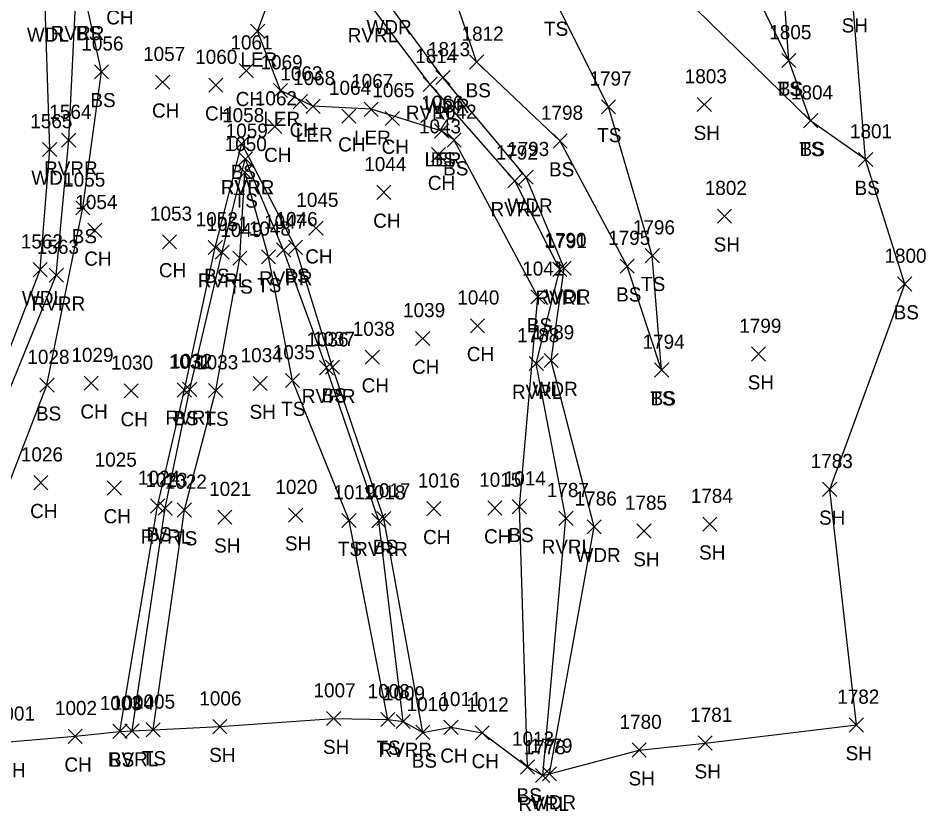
# Model space of a CAD drawing. Extents: x 1600281 to 1602254, y 862855 to 863227.
# Drawn here: x 1602106.5 to 1602234.8, y 862869.5 to 862981.5 of the extents above; entities that cross this region are included whole.
import ezdxf

# ---------------------------------------------------------------- set-up
doc = ezdxf.new("R2010")
doc.units = 0
for name, color, linetype in [('L_A', 7, 'Continuous'), ('L_I', 7, 'Continuous'), ('L_TIC', 7, 'Continuous'), ('LARO', 7, 'Continuous'), ('LAWA', 7, 'Continuous'), ('LAWE', 7, 'Continuous'), ('LELB', 7, 'Continuous'), ('LSOGP', 7, 'Continuous')]:
    doc.layers.add(name, color=color, linetype=linetype)

msp = doc.modelspace()

# ---------------------------------------------------------------- linework, layer by layer
at = {"layer": 'L_TIC'}
for points in [[(1602139.35, 862978.68), (1602141.35, 862980.68)], [(1602141.35, 862978.68), (1602139.35, 862980.68)], [(1602170.3, 862974.32), (1602172.3, 862976.32)], [(1602172.3, 862974.32), (1602170.3, 862976.32)], [(1602214.42, 862974.54), (1602216.42, 862976.54)], [(1602216.42, 862974.54), (1602214.42, 862976.54)], [(1602214.42, 862974.54), (1602216.42, 862976.54)], [(1602216.42, 862974.54), (1602214.42, 862976.54)], [(1602117.28, 862972.93), (1602119.28, 862974.93)], [(1602119.28, 862972.93), (1602117.28, 862974.93)], [(1602137.76, 862973.09), (1602139.76, 862975.09)], [(1602139.76, 862973.09), (1602137.76, 862975.09)], [(1602125.94, 862971.46), (1602127.94, 862973.46)], [(1602127.94, 862971.46), (1602125.94, 862973.46)], [(1602165.54, 862972.13), (1602167.54, 862974.13)], [(1602167.54, 862972.13), (1602165.54, 862974.13)], [(1602133.44, 862971.05), (1602135.44, 862973.05)], [(1602135.44, 862971.05), (1602133.44, 862973.05)], [(1602142.59, 862970.28), (1602144.59, 862972.28)], [(1602144.59, 862970.28), (1602142.59, 862972.28)], [(1602163.73, 862971.16), (1602165.73, 862973.16)], [(1602165.73, 862971.16), (1602163.73, 862973.16)], [(1602145.38, 862968.71), (1602147.38, 862970.71)], [(1602147.38, 862968.71), (1602145.38, 862970.71)], [(1602147.17, 862968.06), (1602149.17, 862970.06)], [(1602149.17, 862968.06), (1602147.17, 862970.06)], [(1602155.39, 862967.63), (1602157.39, 862969.63)], [(1602157.39, 862967.63), (1602155.39, 862969.63)], [(1602188.93, 862967.99), (1602190.93, 862969.99)], [(1602190.93, 862967.99), (1602188.93, 862969.99)], [(1602202.47, 862968.3), (1602204.47, 862970.3)], [(1602204.47, 862968.3), (1602202.47, 862970.3)], [(1602152.25, 862966.67), (1602154.25, 862968.67)], [(1602154.25, 862966.67), (1602152.25, 862968.67)], [(1602158.38, 862966.34), (1602160.38, 862968.34)], [(1602160.38, 862966.34), (1602158.38, 862968.34)], [(1602141.78, 862965.19), (1602143.78, 862967.19)], [(1602143.78, 862965.19), (1602141.78, 862967.19)], [(1602217.49, 862966.02), (1602219.49, 862968.02)], [(1602219.49, 862966.02), (1602217.49, 862968.02)], [(1602217.49, 862966.02), (1602219.49, 862968.02)], [(1602219.49, 862966.02), (1602217.49, 862968.02)], [(1602165.36, 862964.56), (1602167.36, 862966.56)], [(1602167.36, 862964.56), (1602165.36, 862966.56)], [(1602165.36, 862964.56), (1602167.36, 862966.56)], [(1602167.36, 862964.56), (1602165.36, 862966.56)], [(1602112.66, 862963.28), (1602114.66, 862965.28)], [(1602114.66, 862963.28), (1602112.66, 862965.28)], [(1602137.1, 862962.8), (1602139.1, 862964.8)], [(1602139.1, 862962.8), (1602137.1, 862964.8)], [(1602137.1, 862962.8), (1602139.1, 862964.8)], [(1602139.1, 862962.8), (1602137.1, 862964.8)], [(1602167.13, 862963.29), (1602169.13, 862965.29)], [(1602169.13, 862963.29), (1602167.13, 862965.29)], [(1602182.09, 862963.15), (1602184.09, 862965.15)], [(1602184.09, 862963.15), (1602182.09, 862965.15)], [(1602109.97, 862961.96), (1602111.97, 862963.96)], [(1602111.97, 862961.96), (1602109.97, 862963.96)], [(1602164.91, 862961.23), (1602166.91, 862963.23)], [(1602166.91, 862961.23), (1602164.91, 862963.23)], [(1602137.61, 862960.62), (1602139.61, 862962.62)], [(1602139.61, 862960.62), (1602137.61, 862962.62)], [(1602137.61, 862960.62), (1602139.61, 862962.62)], [(1602139.61, 862960.62), (1602137.61, 862962.62)], [(1602225.26, 862960.53), (1602227.26, 862962.53)], [(1602227.26, 862960.53), (1602225.26, 862962.53)], [(1602137.56, 862958.73), (1602139.56, 862960.73)], [(1602139.56, 862958.73), (1602137.56, 862960.73)], [(1602137.56, 862958.73), (1602139.56, 862960.73)], [(1602139.56, 862958.73), (1602137.56, 862960.73)], [(1602175.69, 862957.52), (1602177.69, 862959.52)], [(1602177.69, 862957.52), (1602175.69, 862959.52)], [(1602177.29, 862958.03), (1602179.29, 862960.03)], [(1602179.29, 862958.03), (1602177.29, 862960.03)], [(1602157.19, 862955.89), (1602159.19, 862957.89)], [(1602159.19, 862955.89), (1602157.19, 862957.89)], [(1602114.65, 862953.7), (1602116.65, 862955.7)], [(1602116.65, 862953.7), (1602114.65, 862955.7)], [(1602205.31, 862952.53), (1602207.31, 862954.53)], [(1602207.31, 862952.53), (1602205.31, 862954.53)], [(1602147.59, 862950.84), (1602149.59, 862952.84)], [(1602149.59, 862950.84), (1602147.59, 862952.84)], [(1602116.36, 862950.53), (1602118.36, 862952.53)], [(1602118.36, 862950.53), (1602116.36, 862952.53)], [(1602126.91, 862948.89), (1602128.91, 862950.89)], [(1602128.91, 862948.89), (1602126.91, 862950.89)], [(1602133.37, 862948.1), (1602135.37, 862950.1)], [(1602135.37, 862948.1), (1602133.37, 862950.1)], [(1602144.7, 862948.12), (1602146.7, 862950.12)], [(1602146.7, 862948.12), (1602144.7, 862950.12)], [(1602134.34, 862947.45), (1602136.34, 862949.45)], [(1602136.34, 862947.45), (1602134.34, 862949.45)], [(1602143.03, 862947.74), (1602145.03, 862949.74)], [(1602145.03, 862947.74), (1602143.03, 862949.74)], [(1602195.12, 862946.95), (1602197.12, 862948.95)], [(1602197.12, 862946.95), (1602195.12, 862948.95)], [(1602136.85, 862946.58), (1602138.85, 862948.58)], [(1602138.85, 862946.58), (1602136.85, 862948.58)], [(1602140.88, 862946.78), (1602142.88, 862948.78)], [(1602142.88, 862946.78), (1602140.88, 862948.78)], [(1602108.63, 862944.96), (1602110.63, 862946.96)], [(1602110.63, 862944.96), (1602108.63, 862946.96)], [(1602182.06, 862945.01), (1602184.06, 862947.01)], [(1602184.06, 862945.01), (1602182.06, 862947.01)], [(1602182.65, 862945.17), (1602184.65, 862947.17)], [(1602184.65, 862945.17), (1602182.65, 862947.17)], [(1602191.57, 862945.47), (1602193.57, 862947.47)], [(1602193.57, 862945.47), (1602191.57, 862947.47)], [(1602110.9, 862944.19), (1602112.9, 862946.19)], [(1602112.9, 862944.19), (1602110.9, 862946.19)], [(1602230.78, 862942.94), (1602232.78, 862944.94)], [(1602232.78, 862942.94), (1602230.78, 862944.94)], [(1602178.94, 862941.12), (1602180.94, 862943.12)], [(1602180.94, 862941.12), (1602178.94, 862943.12)], [(1602170.42, 862937.04), (1602172.42, 862939.04)], [(1602172.42, 862937.04), (1602170.42, 862939.04)], [(1602162.68, 862935.25), (1602164.68, 862937.25)], [(1602164.68, 862935.25), (1602162.68, 862937.25)], [(1602210.12, 862933.04), (1602212.12, 862935.04)], [(1602212.12, 862933.04), (1602210.12, 862935.04)], [(1602155.56, 862932.61), (1602157.56, 862934.61)], [(1602157.56, 862932.61), (1602155.56, 862934.61)], [(1602178.73, 862931.7), (1602180.73, 862933.7)], [(1602180.73, 862931.7), (1602178.73, 862933.7)], [(1602180.84, 862932.12), (1602182.84, 862934.12)], [(1602182.84, 862932.12), (1602180.84, 862934.12)], [(1602149.09, 862931.11), (1602151.09, 862933.11)], [(1602151.09, 862931.11), (1602149.09, 862933.11)], [(1602149.94, 862931.2), (1602151.94, 862933.2)], [(1602151.94, 862931.2), (1602149.94, 862933.2)], [(1602196.44, 862930.78), (1602198.44, 862932.78)], [(1602198.44, 862930.78), (1602196.44, 862932.78)], [(1602196.44, 862930.78), (1602198.44, 862932.78)], [(1602198.44, 862930.78), (1602196.44, 862932.78)], [(1602115.82, 862928.92), (1602117.82, 862930.92)], [(1602117.82, 862928.92), (1602115.82, 862930.92)], [(1602139.72, 862928.88), (1602141.72, 862930.88)], [(1602141.72, 862928.88), (1602139.72, 862930.88)], [(1602144.27, 862929.3), (1602146.27, 862931.3)], [(1602146.27, 862929.3), (1602144.27, 862931.3)], [(1602109.59, 862928.64), (1602111.59, 862930.64)], [(1602111.59, 862928.64), (1602109.59, 862930.64)], [(1602121.49, 862927.83), (1602123.49, 862929.83)], [(1602123.49, 862927.83), (1602121.49, 862929.83)], [(1602129, 862927.97), (1602131, 862929.97)], [(1602131, 862927.97), (1602129, 862929.97)], [(1602129.76, 862928.06), (1602131.76, 862930.06)], [(1602131.76, 862928.06), (1602129.76, 862930.06)], [(1602133.43, 862927.88), (1602135.43, 862929.88)], [(1602135.43, 862927.88), (1602133.43, 862929.88)], [(1602108.73, 862914.86), (1602110.73, 862916.86)], [(1602110.73, 862914.86), (1602108.73, 862916.86)], [(1602119.1, 862914.12), (1602121.1, 862916.12)], [(1602121.1, 862914.12), (1602119.1, 862916.12)], [(1602220.19, 862913.92), (1602222.19, 862915.92)], [(1602222.19, 862913.92), (1602220.19, 862915.92)], [(1602125.22, 862911.56), (1602127.22, 862913.56)], [(1602127.22, 862911.56), (1602125.22, 862913.56)], [(1602126.28, 862911.25), (1602128.28, 862913.25)], [(1602128.28, 862911.25), (1602126.28, 862913.25)], [(1602129, 862911), (1602131, 862913)], [(1602131, 862911), (1602129, 862913)], [(1602164.25, 862911.18), (1602166.25, 862913.18)], [(1602166.25, 862911.18), (1602164.25, 862913.18)], [(1602172.86, 862911.28), (1602174.86, 862913.28)], [(1602174.86, 862911.28), (1602172.86, 862913.28)], [(1602176.34, 862911.47), (1602178.34, 862913.47)], [(1602178.34, 862911.47), (1602176.34, 862913.47)], [(1602134.71, 862909.98), (1602136.71, 862911.98)], [(1602136.71, 862909.98), (1602134.71, 862911.98)], [(1602144.72, 862910.28), (1602146.72, 862912.28)], [(1602146.72, 862910.28), (1602144.72, 862912.28)], [(1602157.19, 862909.79), (1602159.19, 862911.79)], [(1602159.19, 862909.79), (1602157.19, 862911.79)], [(1602182.92, 862909.83), (1602184.92, 862911.83)], [(1602184.92, 862909.83), (1602182.92, 862911.83)], [(1602152.27, 862909.51), (1602154.27, 862911.51)], [(1602154.27, 862909.51), (1602152.27, 862911.51)], [(1602156.49, 862909.49), (1602158.49, 862911.49)], [(1602158.49, 862909.49), (1602156.49, 862911.49)], [(1602186.9, 862908.63), (1602188.9, 862910.63)], [(1602188.9, 862908.63), (1602186.9, 862910.63)], [(1602203.24, 862909), (1602205.24, 862911)], [(1602205.24, 862909), (1602203.24, 862911)], [(1602193.94, 862908.04), (1602195.94, 862910.04)], [(1602195.94, 862908.04), (1602193.94, 862910.04)], [(1602150.1, 862881.52), (1602152.1, 862883.52)], [(1602152.1, 862881.52), (1602150.1, 862883.52)], [(1602134.02, 862880.38), (1602136.02, 862882.38)], [(1602136.02, 862880.38), (1602134.02, 862882.38)], [(1602157.75, 862881.4), (1602159.75, 862883.4)], [(1602159.75, 862881.4), (1602157.75, 862883.4)], [(1602159.91, 862881.1), (1602161.91, 862883.1)], [(1602161.91, 862881.1), (1602159.91, 862883.1)], [(1602166.67, 862880.29), (1602168.67, 862882.29)], [(1602168.67, 862880.29), (1602166.67, 862882.29)], [(1602223.95, 862880.62), (1602225.95, 862882.62)], [(1602225.95, 862880.62), (1602223.95, 862882.62)], [(1602113.56, 862879.02), (1602115.56, 862881.02)], [(1602115.56, 862879.02), (1602113.56, 862881.02)], [(1602119.9, 862879.71), (1602121.9, 862881.71)], [(1602121.9, 862879.71), (1602119.9, 862881.71)], [(1602121.61, 862879.77), (1602123.61, 862881.77)], [(1602123.61, 862879.77), (1602121.61, 862881.77)], [(1602124.59, 862879.92), (1602126.59, 862881.92)], [(1602126.59, 862879.92), (1602124.59, 862881.92)], [(1602162.69, 862879.57), (1602164.69, 862881.57)], [(1602164.69, 862879.57), (1602162.69, 862881.57)], [(1602171.09, 862879.51), (1602173.09, 862881.51)], [(1602173.09, 862879.51), (1602171.09, 862881.51)], [(1602202.6, 862878.06), (1602204.6, 862880.06)], [(1602204.6, 862878.06), (1602202.6, 862880.06)], [(1602193.27, 862877.07), (1602195.27, 862879.07)], [(1602195.27, 862877.07), (1602193.27, 862879.07)], [(1602177.49, 862874.68), (1602179.49, 862876.68)], [(1602179.49, 862874.68), (1602177.49, 862876.68)], [(1602179.63, 862873.48), (1602181.63, 862875.48)], [(1602181.63, 862873.48), (1602179.63, 862875.48)], [(1602180.59, 862873.7), (1602182.59, 862875.7)], [(1602182.59, 862873.7), (1602180.59, 862875.7)]]:
    msp.add_lwpolyline(points, dxfattribs=at)
at = {"layer": 'LARO'}
msp.add_lwpolyline([(1602166.36, 862965.56), (1602156.39, 862968.63), (1602148.17, 862969.06), (1602143.59, 862971.28), (1602140.35, 862979.68), (1602143.24, 862987.55), (1602146.6, 862992.78)], dxfattribs=at)
at = {"layer": 'LAWA'}
for points in [[(1602181.59, 862874.7), (1602187.9, 862909.63), (1602181.84, 862933.12), (1602183.65, 862946.17), (1602178.29, 862959.03), (1602166.54, 862973.13), (1602158.38, 862984.25), (1602153.07, 863003.85), (1602148.74, 863019.56), (1602142.31, 863032.97), (1602127.68, 863047.24), (1602113.21, 863058.06), (1602100.07, 863063.24), (1602085.95, 863068.22)], [(1602096.41, 862879.64), (1602095.37, 862902.03), (1602099.33, 862919.26), (1602109.63, 862945.96), (1602110.97, 862962.96), (1602110.33, 862983.19), (1602104.7, 862999.6), (1602098.83, 863009.48), (1602089.05, 863018.84), (1602087.06, 863019.48), (1602084.93, 863020.57), (1602083.85, 863020.87), (1602075.62, 863029.36), (1602062.85, 863014.97)]]:
    msp.add_lwpolyline(points, dxfattribs=at)
at = {"layer": 'LAWE'}
for points in [[(1602180.63, 862874.48), (1602183.92, 862910.83), (1602179.73, 862932.7), (1602183.06, 862946.01), (1602176.69, 862958.52), (1602164.73, 862972.16), (1602156.51, 862983.11), (1602149.65, 863002.93), (1602145.18, 863017.68), (1602136.97, 863030.89), (1602125.37, 863045.7), (1602111.62, 863056.89), (1602099.97, 863060.68), (1602084.89, 863067.15), (1602071.85, 863075.33)], [(1602098.44, 862879.18), (1602097.38, 862900.93), (1602100.82, 862918.12), (1602111.9, 862945.19), (1602113.66, 862964.28), (1602114.6, 862983.41), (1602109.05, 863000.36), (1602100.6, 863011.38), (1602088.42, 863022.64), (1602086.17, 863023.52), (1602076.98, 863030.19), (1602067.14, 863035), (1602054.87, 863040.58)], [(1602122.61, 862880.77), (1602127.28, 862912.25), (1602130.76, 862929.06), (1602135.34, 862948.45), (1602138.61, 862961.62)], [(1602160.91, 862882.1), (1602157.49, 862910.49), (1602150.09, 862932.11), (1602144.03, 862948.74), (1602138.61, 862961.62)]]:
    msp.add_lwpolyline(points, dxfattribs=at)
at = {"layer": 'LELB'}
for points in [[(1602231.78, 862943.94), (1602226.26, 862961.53), (1602218.49, 862967.02), (1602194.13, 862990.83), (1602188.47, 863004.89), (1602184.54, 863016.14), (1602188.04, 863030.7), (1602174.95, 863034.2), (1602162.97, 863042.41), (1602150.21, 863055.3), (1602142.82, 863056.75), (1602118.66, 863061.18), (1602100.07, 863063.24)], [(1602197.44, 862931.78), (1602196.12, 862947.95), (1602189.93, 862968.99), (1602182.41, 862984.02), (1602177.66, 862997.92), (1602171.58, 863018.35), (1602165.76, 863027.59), (1602159.48, 863036.07), (1602148.99, 863052.05), (1602142.82, 863056.75)], [(1602099.84, 862878.35), (1602100.95, 862904.78), (1602110.59, 862929.64), (1602115.65, 862954.7), (1602118.28, 862973.93), (1602116.24, 862983.39), (1602108.04, 863004.49), (1602102.91, 863010.99), (1602095.9, 863019.12), (1602089.35, 863024.5), (1602085.54, 863025.45), (1602074.55, 863034.5), (1602069.63, 863039.23), (1602052.34, 863044.6)], [(1602197.44, 862931.78), (1602192.57, 862946.47), (1602183.09, 862964.15), (1602171.3, 862975.32), (1602165.37, 862992.89), (1602160.67, 863007.68), (1602154.53, 863022.83), (1602142.31, 863032.97)], [(1602215.42, 862975.54), (1602213.66, 862999.86), (1602215.3, 863016.73), (1602234.46, 863031.08), (1602218.77, 863031.21), (1602203.52, 863031.33), (1602188.04, 863030.7)], [(1602218.49, 862967.02), (1602215.42, 862975.54), (1602199.31, 863008.25), (1602190.74, 863017.05), (1602203.52, 863031.33)], [(1602178.49, 862875.68), (1602177.34, 862912.47), (1602179.94, 862942.12), (1602168.13, 862964.29), (1602166.36, 862965.56)], [(1602120.9, 862880.71), (1602126.22, 862912.56), (1602130, 862928.97), (1602134.37, 862949.1), (1602138.1, 862963.8)], [(1602163.69, 862880.57), (1602158.19, 862910.79), (1602150.94, 862932.2), (1602145.7, 862949.12), (1602138.1, 862963.8)], [(1602125.59, 862880.92), (1602130, 862912), (1602134.43, 862928.88), (1602137.85, 862947.58), (1602138.56, 862959.73)], [(1602158.75, 862882.4), (1602153.27, 862910.51), (1602145.27, 862930.3), (1602141.88, 862947.78), (1602138.56, 862959.73)]]:
    msp.add_lwpolyline(points, dxfattribs=at)
at = {"layer": 'LSOGP'}
msp.add_lwpolyline([(1602105.22, 862879.24), (1602114.56, 862880.02), (1602120.9, 862880.71), (1602122.61, 862880.77), (1602125.59, 862880.92), (1602135.02, 862881.38), (1602151.1, 862882.52), (1602158.75, 862882.4), (1602160.91, 862882.1), (1602163.69, 862880.57), (1602167.67, 862881.29), (1602172.09, 862880.51), (1602178.49, 862875.68), (1602180.63, 862874.48), (1602181.59, 862874.7), (1602194.27, 862878.07), (1602203.6, 862879.06), (1602224.95, 862881.62), (1602221.19, 862914.92), (1602231.78, 862943.94), (1602226.26, 862961.53), (1602224.39, 862984.49)], dxfattribs=at)

# ---------------------------------------------------------------- texts
at = {"layer": 'L_A'}
for s, p in [('CH', (1602118.96, 862980.63)), ('WDR', (1602155.74, 862979.25)), ('TS', (1602180.82, 862979.02)), ('SH', (1602222.88, 862979.49)), ('WDL', (1602107.75, 862978.19)), ('RVRR', (1602111.11, 862978.41)), ('BS', (1602114.68, 862978.39)), ('RVRL', (1602153.08, 862978.11)), ('LER', (1602137.93, 862974.68)), ('BS', (1602169.74, 862970.32)), ('TS', (1602213.83, 862970.54)), ('BS', (1602213.86, 862970.54)), ('BS', (1602116.72, 862968.93)), ('CH', (1602137.25, 862969.09)), ('CH', (1602125.43, 862967.46)), ('WDR', (1602163.91, 862968.13)), ('CH', (1602132.92, 862967.05)), ('LER', (1602141.17, 862966.28)), ('RVRL', (1602161.3, 862967.16)), ('CH', (1602144.87, 862964.71)), ('LER', (1602145.76, 862964.06)), ('LER', (1602153.97, 862963.63)), ('TS', (1602188.34, 862963.99)), ('SH', (1602201.96, 862964.3)), ('CH', (1602151.73, 862962.67)), ('CH', (1602157.87, 862962.34)), ('CH', (1602141.27, 862961.19)), ('TS', (1602216.89, 862962.02)), ('BS', (1602216.93, 862962.02)), ('LER', (1602163.94, 862960.56)), ('BS', (1602164.8, 862960.56)), ('RVRR', (1602110.17, 862959.28)), ('BS', (1602136.54, 862958.8)), ('BS', (1602136.54, 862958.8)), ('BS', (1602166.57, 862959.29)), ('BS', (1602181.53, 862959.15)), ('WDL', (1602108.38, 862957.96)), ('CH', (1602164.4, 862957.23)), ('RVRR', (1602135.13, 862956.62)), ('RVRL', (1602135.18, 862956.62)), ('BS', (1602224.7, 862956.53)), ('TS', (1602136.97, 862954.73)), ('TS', (1602136.97, 862954.73)), ('RVRL', (1602173.26, 862953.52)), ('WDR', (1602175.65, 862954.03)), ('CH', (1602156.68, 862951.89)), ('BS', (1602114.09, 862949.7)), ('SH', (1602204.79, 862948.53)), ('CH', (1602147.08, 862946.84)), ('CH', (1602115.85, 862946.53)), ('CH', (1602126.4, 862944.89)), ('RVRL', (1602131.91, 862943.45)), ('BS', (1602132.81, 862944.1)), ('RVRR', (1602140.54, 862943.74)), ('BS', (1602144.14, 862944.12)), ('TS', (1602194.53, 862942.95)), ('TS', (1602136.26, 862942.58)), ('TS', (1602140.29, 862942.78)), ('WDL', (1602107.05, 862940.96)), ('RVRL', (1602179.63, 862941.01)), ('WDR', (1602181.01, 862941.17)), ('BS', (1602191.01, 862941.47)), ('RVRR', (1602108.41, 862940.19)), ('BS', (1602230.22, 862938.94)), ('BS', (1602178.39, 862937.12)), ('CH', (1602169.91, 862933.04)), ('CH', (1602162.17, 862931.25)), ('SH', (1602209.6, 862929.04)), ('CH', (1602155.05, 862928.61)), ('RVRL', (1602176.29, 862927.7)), ('WDR', (1602179.2, 862928.12)), ('RVRR', (1602146.6, 862927.11)), ('BS', (1602149.38, 862927.2)), ('TS', (1602195.85, 862926.78)), ('BS', (1602195.88, 862926.78)), ('TS', (1602143.68, 862925.3)), ('BS', (1602109.03, 862924.64)), ('CH', (1602115.31, 862924.92)), ('CH', (1602120.98, 862923.83)), ('RVRL', (1602127.33, 862924.06)), ('BS', (1602128.44, 862923.97)), ('TS', (1602132.84, 862923.88)), ('SH', (1602139.21, 862924.88)), ('CH', (1602108.21, 862910.86)), ('CH', (1602118.59, 862910.12)), ('SH', (1602219.68, 862909.92)), ('RVRL', (1602123.84, 862907.25)), ('BS', (1602124.66, 862907.56)), ('CH', (1602163.74, 862907.18)), ('CH', (1602172.35, 862907.28)), ('BS', (1602175.78, 862907.47)), ('TS', (1602128.41, 862907)), ('SH', (1602134.2, 862905.98)), ('SH', (1602144.21, 862906.28)), ('BS', (1602156.63, 862905.79)), ('RVRL', (1602180.48, 862905.83)), ('TS', (1602151.68, 862905.51)), ('RVRR', (1602154, 862905.49)), ('WDR', (1602185.26, 862904.63)), ('SH', (1602202.73, 862905)), ('SH', (1602193.43, 862904.04)), ('SH', (1602133.51, 862876.38)), ('SH', (1602149.59, 862877.52)), ('TS', (1602157.16, 862877.4)), ('RVRR', (1602157.43, 862877.1)), ('CH', (1602166.16, 862876.29)), ('SH', (1602223.43, 862876.62)), ('CH', (1602113.05, 862875.02)), ('RVRL', (1602119.18, 862875.77)), ('BS', (1602119.35, 862875.71)), ('TS', (1602124, 862875.92)), ('BS', (1602162.13, 862875.57)), ('CH', (1602170.58, 862875.51)), ('CH', (1602103.71, 862874.24)), ('SH', (1602202.09, 862874.06)), ('SH', (1602192.76, 862873.07)), ('BS', (1602176.94, 862870.68)), ('RVRL', (1602177.2, 862869.48)), ('WDR', (1602178.95, 862869.7))]:
    msp.add_text(s, height=2, dxfattribs=at).set_placement(p)
at = {"layer": 'L_I'}
for s, p in [('1812', (1602169.17, 862978.32)), ('1805', (1602212.65, 862978.54)), ('1805', (1602212.65, 862978.54)), ('1056', (1602115.45, 862976.93)), ('1061', (1602136.51, 862977.09)), ('1057', (1602124.17, 862975.46)), ('1060', (1602131.53, 862975.05)), ('1814', (1602162.61, 862975.16)), ('1813', (1602164.42, 862976.13)), ('1069', (1602140.76, 862974.28)), ('1063', (1602143.56, 862972.71)), ('1068', (1602145.36, 862972.06)), ('1067', (1602153.57, 862971.63)), ('1797', (1602187.24, 862971.99)), ('1803', (1602200.7, 862972.3)), ('1064', (1602150.43, 862970.67)), ('1065', (1602156.56, 862970.34)), ('1804', (1602215.71, 862970.02)), ('1804', (1602215.71, 862970.02)), ('1062', (1602139.96, 862969.19)), ('1066', (1602163.48, 862968.56)), ('1066', (1602163.48, 862968.56)), ('1564', (1602110.92, 862967.28)), ('1058', (1602135.33, 862966.8)), ('1058', (1602135.33, 862966.8)), ('1042', (1602165.35, 862967.29)), ('1798', (1602180.39, 862967.15)), ('1565', (1602108.23, 862965.96)), ('1043', (1602163.14, 862965.23)), ('1059', (1602135.84, 862964.62)), ('1059', (1602135.84, 862964.62)), ('1801', (1602224.05, 862964.53)), ('1050', (1602135.7, 862962.73)), ('1050', (1602135.7, 862962.73)), ('1792', (1602174, 862961.52)), ('1793', (1602175.6, 862962.03)), ('1044', (1602155.42, 862959.89)), ('1055', (1602112.88, 862957.7)), ('1802', (1602203.53, 862956.53)), ('1054', (1602114.59, 862954.53)), ('1045', (1602145.82, 862954.84)), ('1053', (1602125.14, 862952.89)), ('1052', (1602131.6, 862952.1)), ('1046', (1602142.88, 862952.12)), ('1051', (1602133.14, 862951.45)), ('1048', (1602139.11, 862950.78)), ('1047', (1602141.26, 862951.74)), ('1796', (1602193.37, 862950.95)), ('1049', (1602135.07, 862950.58)), ('1795', (1602189.88, 862949.47)), ('1562', (1602106.89, 862948.96)), ('1563', (1602109.16, 862948.19)), ('1790', (1602180.87, 862949.17)), ('1791', (1602180.93, 862949.01)), ('1800', (1602228.92, 862946.94)), ('1041', (1602177.74, 862945.12)), ('1040', (1602168.56, 862941.04)), ('1039', (1602160.9, 862939.25)), ('1038', (1602153.79, 862936.61)), ('1799', (1602208.41, 862937.04)), ('1788', (1602177.03, 862935.7)), ('1789', (1602179.14, 862936.12)), ('1036', (1602147.26, 862935.11)), ('1037', (1602148.17, 862935.2)), ('1794', (1602194.74, 862934.78)), ('1794', (1602194.74, 862934.78)), ('1029', (1602114.04, 862932.92)), ('1034', (1602137.95, 862932.88)), ('1035', (1602142.5, 862933.3)), ('1028', (1602107.82, 862932.64)), ('1030', (1602119.64, 862931.83)), ('1031', (1602127.8, 862931.97)), ('1032', (1602127.99, 862932.06)), ('1033', (1602131.66, 862931.88)), ('1026', (1602106.9, 862918.86)), ('1025', (1602117.33, 862918.12)), ('1783', (1602218.5, 862917.92)), ('1024', (1602123.44, 862915.56)), ('1023', (1602124.5, 862915.25)), ('1022', (1602127.23, 862915)), ('1016', (1602162.99, 862915.18)), ('1015', (1602171.66, 862915.28)), ('1014', (1602175.13, 862915.47)), ('1021', (1602133.5, 862913.98)), ('1020', (1602142.86, 862914.28)), ('1019', (1602151.05, 862913.51)), ('1018', (1602155.28, 862913.49)), ('1017', (1602155.99, 862913.79)), ('1787', (1602181.22, 862913.83)), ('1786', (1602185.15, 862912.63)), ('1784', (1602201.55, 862913)), ('1785', (1602192.25, 862912.04)), ('1007', (1602148.25, 862885.52)), ('1008', (1602155.9, 862885.4)), ('1006', (1602132.11, 862884.38)), ('1009', (1602158.06, 862885.1)), ('1011', (1602166.03, 862884.29)), ('1782', (1602222.25, 862884.62)), ('1002', (1602111.71, 862883.02)), ('1003', (1602118.05, 862883.71)), ('1004', (1602119.76, 862883.77)), ('1005', (1602122.74, 862883.92)), ('1010', (1602161.4, 862883.57)), ('1012', (1602169.88, 862883.51)), ('1001', (1602102.94, 862882.24)), ('1781', (1602201.47, 862882.06)), ('1780', (1602191.49, 862881.07)), ('1013', (1602176.29, 862878.68)), ('1779', (1602178.89, 862877.7)), ('1778', (1602177.94, 862877.48))]:
    msp.add_text(s, height=2, dxfattribs=at).set_placement(p)

doc.saveas('drawing.dxf')
